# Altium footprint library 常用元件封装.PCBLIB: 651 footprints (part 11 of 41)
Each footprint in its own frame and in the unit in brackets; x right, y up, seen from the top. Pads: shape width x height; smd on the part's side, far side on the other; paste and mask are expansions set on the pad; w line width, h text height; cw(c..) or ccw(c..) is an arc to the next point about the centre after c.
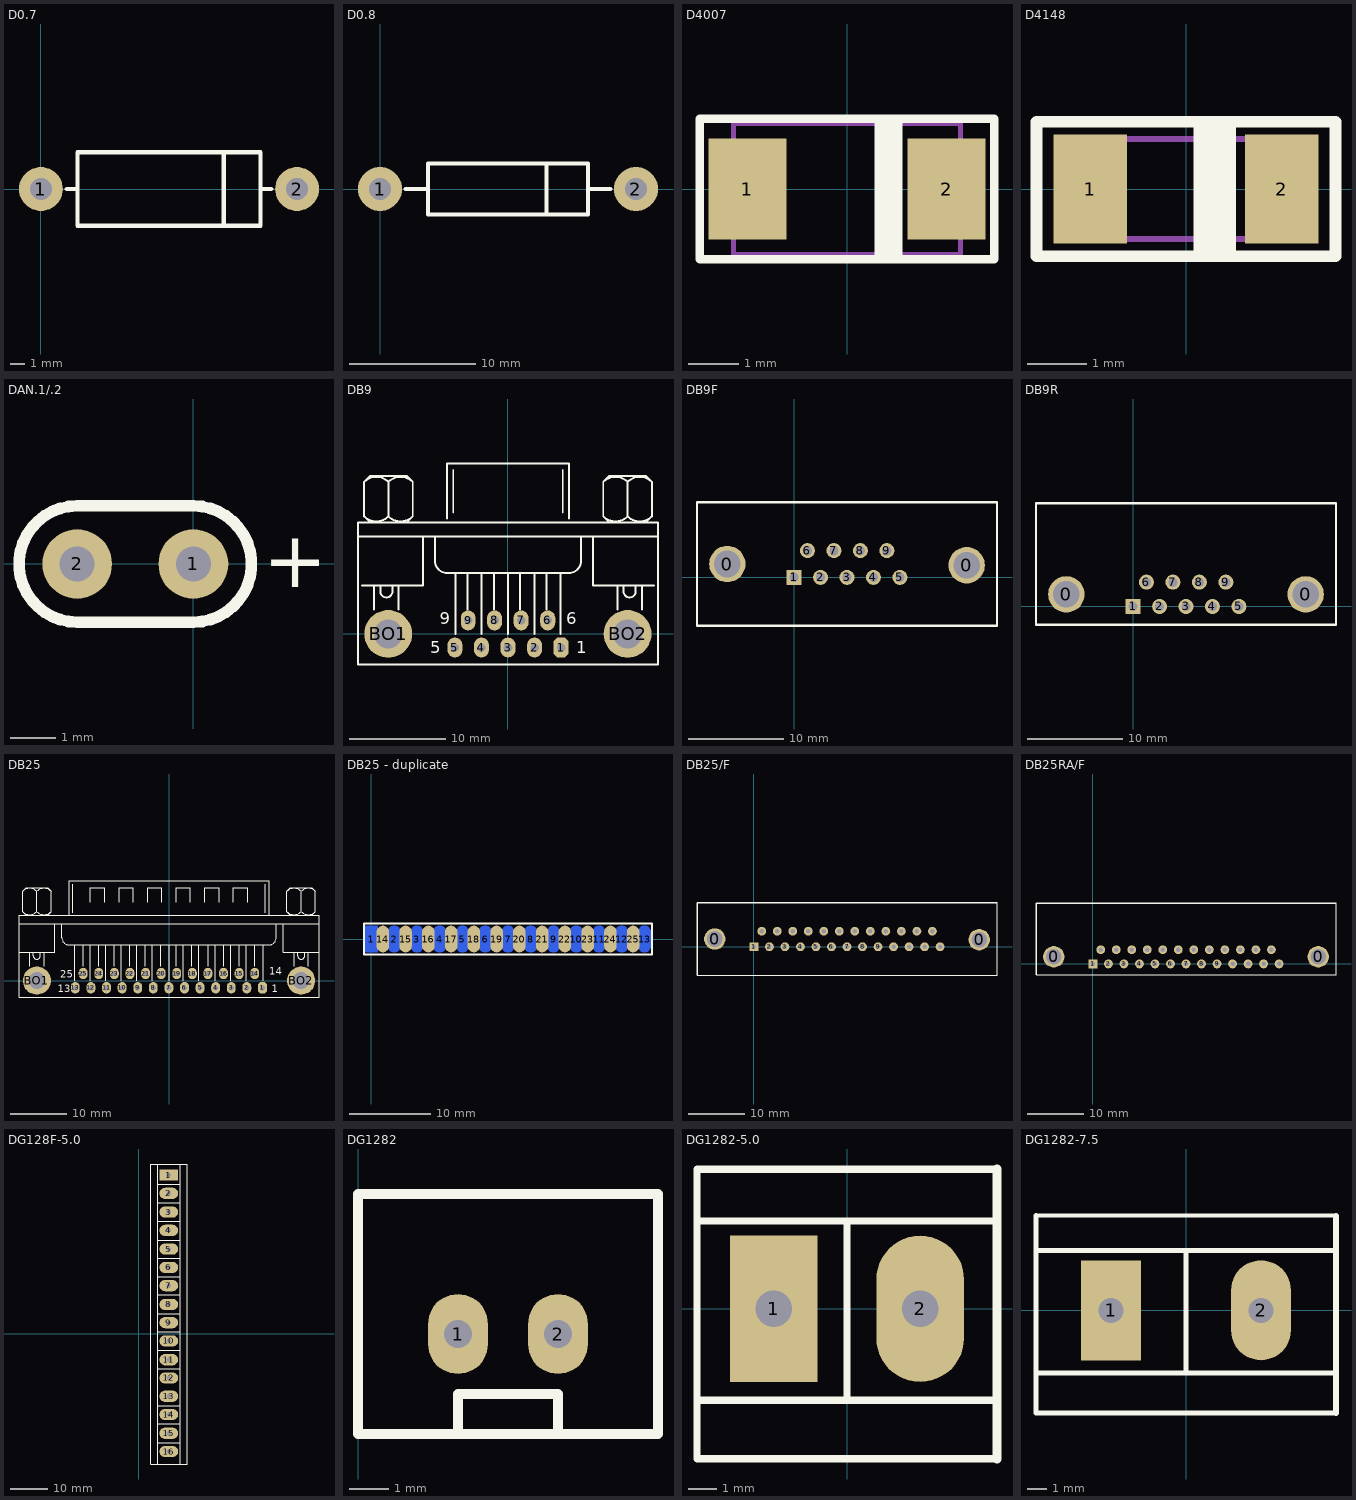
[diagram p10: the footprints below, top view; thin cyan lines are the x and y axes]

## D0.7 [mil] "17.78mm IN6A"
height 236.22
pads (2):
  round 120 hole 60: 1(0,0) 2(700,0)
TopOverlay:
  lines w12: 70,0 100,0 ; 500,-100 500,100 ; 600,0 630,0 ; 100,-100 100,100 600,100 600,-100 100,-100

## D0.8 [mm] "20.32mm"
height 6
pads (2):
  round 3.5 hole 1.78: 1(0,0) 2(20.32,0)
TopOverlay:
  lines w0.305: 2.032,0 3.81,0 ; 13.208,-2.032 13.208,2.032 ; 16.51,0 18.288,0 ; 3.81,-2.032 3.81,2.032 16.51,2.032 16.51,-2.032 3.81,-2.032

## D4007 [mm]
height 2
pads (2):
  rect 1.55x2 smd: 1(-1.975,0) 2(1.975,0)
TopOverlay:
  lines w0.17: 0.635,-1.397 0.635,1.397 ; 0.762,-1.397 0.762,1.397 ; 0.889,-1.397 0.889,1.397 ; 1.016,-1.397 1.016,1.397 ; -2.921,-1.397 2.921,-1.397 2.921,1.397 -2.921,1.397 -2.921,-1.397
Mechanical13:
  lines w0.1: -2.25,-1.3 2.25,-1.3 2.25,1.3 -2.25,1.3 -2.25,-1.3
3D body: height 2, standoff 0, extent -2.25,-1.3 2.25,1.3

## D4148 [mm] "MELF Diode, 2-Leads, Body 3.5x1.7mm, IPC Medium Density"
height 1.7
pads (2):
  rect 1.25x1.85 smd: 1(-1.625,0) 2(1.625,0)
TopOverlay:
  rectangle: 0.127,-1.143 0.854,1.143
  lines w0.2: 0.6,-1.143 2.54,-1.143 2.54,1.143 0.6,1.143 ; 0.762,-1.143 -0.6,-1.143 -2.54,-1.143 -2.54,1.143 -0.6,1.143 0.762,1.143
Mechanical13:
  rectangle: 1.352,-0.85 1.85,0.85
  lines w0.1: -1.85,-0.85 1.85,-0.85 1.85,0.85 -1.85,0.85 -1.85,-0.85
3D body: height 1.7, standoff 0, extent -1.85,-0.85 1.85,0.85

## DAN.1/.2 [mil]
pads (2):
  round 60 hole 30: 1(0,0) 2(-100,0)
TopOverlay:
  lines w10: -100,-50 cw(c-100,0) -100,50 0,50 cw(c0,0) 0,-50 -100,-50
  text "+" at 60,-20 h48

## DB9 [mil]
pads (11):
  oct 62x82 hole 35: 1(218.75,-55.83)
  oval 62x82 hole 35: 2(109.58,-55.83) 3(0.42,-55.83) 4(-108.75,-55.83) 5(-217.92,-55.83) 6(163.75,55.83) 7(54.58,55.83) 8(-54.58,55.83)
  oval 60x82 hole 35: 9(-163.75,55.83)
  round 196.67 hole 118.33: BO1(-492.08,0) BO2(492.08,0)
TopOverlay:
  lines w8: -616.25,400 617.08,400 ; -599.58,200 -349.58,200 -349.58,400 ; -591.34,483.25 ccw(c-541.25,533.33) -491.16,483.25 ; -591.34,625.09 cw(c-541.25,575) -491.16,625.09 ; -566.25,458.33 -591.25,483.33 -591.25,625 -566.25,650 -416.25,650 -391.25,625 -391.25,483.33 -416.25,458.33 ; -549.58,100 -549.58,200 ; -524.58,200 -524.58,175 ccw(c-499.58,175) -474.58,175 -474.58,200 ; -491.34,483.25 ccw(c-441.25,533.33) -391.16,483.25 ; -491.34,625.09 cw(c-441.25,575) -391.16,625.09 ; -491.25,483.33 -491.25,625 ; -449.58,100 -449.58,200 ; -299.58,400 -299.58,300 ccw(c-249.58,300) -249.58,250 250.42,250 ccw(c250.42,300) 300.42,300 300.42,400 ; -249.58,475 -249.58,700 250.42,700 250.42,475 ; -224.58,500 -224.58,675 ; -216.25,0 -216.25,250 ; -166.25,100 -166.25,250 ; -107.92,0 -107.92,250 ; -57.92,100 -57.92,250 ; 0.42,0 0.42,250 ; 50.42,100 50.42,250 ; 108.75,0 108.75,250 ; 158.75,100 158.75,250 ; 217.08,0 217.08,250 ; 225.42,500 225.42,675 ; 350.42,400 350.42,200 600.42,200 ; 392,483.25 ccw(c442.08,533.33) 492.17,483.25 ; 392,625.09 cw(c442.08,575) 492.17,625.09 ; 417.08,458.33 392.08,483.33 392.08,625 417.08,650 567.08,650 592.08,625 592.08,483.33 567.08,458.33 ; 450.42,100 450.42,200 ; 475.42,200 475.42,175 ccw(c500.42,175) 525.42,175 525.42,200 ; 492,483.25 ccw(c542.08,533.33) 592.17,483.25 ; 492,625.09 cw(c542.08,575) 592.17,625.09 ; 492.08,483.33 492.08,625 ; 550.42,100 550.42,200 ; -616.25,-125 -616.25,458.33 617.08,458.33 617.08,-125 -616.25,-125
  text "9" at -279.58,40 h50
  text "5" at -319.58,-80 h50
  text "1" at 280.42,-80 h50
  text "6" at 240.42,40 h50

## DB9F [mil]
pads (11):
  round 150 hole 110: 0(-275,55) 0(711,50)
  rect 62x62 hole 38: 1(0,0)
  round 62 hole 38: 2(109,0) 3(218,0) 4(327,0) 5(436,0) 6(55,110) 7(164,110) 8(273,110) 9(382,110)
TopOverlay:
  lines w10: -400,-200 -400,310 836,310 836,-200 -400,-200

## DB9R [mil]
pads (11):
  round 150 hole 110: 0(-275,50) 0(711,50)
  rect 62x62 hole 38: 1(0,0)
  round 62 hole 38: 2(109,0) 3(218,0) 4(327,0) 5(436,0) 6(55,100) 7(164,100) 8(273,100) 9(382,100)
TopOverlay:
  lines w10: -400,-75 -400,425 836,425 836,-75 -400,-75

## DB25 [mil]
pads (27):
  oct 62x80 hole 35: 1(654.17,-50)
  oval 62x80 hole 35: 2(545,-50) 3(435.83,-50) 4(326.67,-50) 5(217.5,-50) 6(108.33,-50) 7(-0.83,-50) 8(-110,-50) 9(-219.17,-50) 10(-328.33,-50) 11(-437.5,-50) 12(-546.67,-50) 13(-655.83,-50) 14(600,50) 15(490.83,50) 16(381.67,50) 17(272.5,50) 18(163.33,50) 19(54.17,50) 20(-55,50) 21(-164.17,50) 22(-273.33,50) 23(-382.5,50) 24(-491.67,50) 25(-600.83,50)
  round 196.67 hole 118.33: BO1(-925,0) BO2(925,0)
TopOverlay:
  lines w8: -1050,200 -800,200 -800,400 ; -1050,400 1050,400 ; -1025.09,483.25 ccw(c-975,533.33) -924.91,483.25 ; -1025.09,625.09 cw(c-975,575) -924.91,625.09 ; -1000,458.33 -1025,483.33 -1025,625 -1000,650 -850,650 -825,625 -825,483.33 -850,458.33 ; -975,100 -975,200 ; -950,200 -950,175 ccw(c-925,175) -900,175 -900,200 ; -925.09,483.25 ccw(c-875,533.33) -824.91,483.25 ; -925.09,625.09 cw(c-875,575) -824.91,625.09 ; -925,483.33 -925,625 ; -875,100 -875,200 ; -750,400 -750,300 ccw(c-700,300) -700,250 700,250 ccw(c700,300) 750,300 750,400 ; -700,458.33 -700,700 700,700 700,458.33 ; -675,475 -675,675 ; -658.33,0 -658.33,250 ; -600,100 -600,250 ; -550,0 -550,250 ; -550,550 -550,650 -450,650 -450,550 ; -491.67,100 -491.67,250 ; -441.67,0 -441.67,250 ; -383.33,100 -383.33,250 ; -350,550 -350,650 -250,650 -250,550 ; -333.33,0 -333.33,250 ; -275,100 -275,250 ; -225,0 -225,250 ; -166.67,100 -166.67,250 ; -150,550 -150,650 -50,650 -50,550 ; -116.67,0 -116.67,250 ; -58.33,100 -58.33,250 ; 0,0 0,250 ; 50,100 50,250 ; 50,550 50,650 150,650 150,550 ; 100,0 100,250 ; 158.33,100 158.33,250 ; 208.33,0 208.33,250 ; 250,550 250,650 350,650 350,550 ; 275,100 275,250 ; 325,0 325,250 ; 383.33,100 383.33,250 ; 433.33,0 433.33,250 ; 450,550 450,650 550,650 550,550 ; 491.67,100 491.67,250 ; 541.67,0 541.67,250 ; 600,100 600,250 ; 658.33,0 658.33,250 ; 675,475 675,675 ; 800,400 800,200 1050,200 ; 824.91,483.25 ccw(c875,533.33) 925.09,483.25 ; 824.91,625.09 cw(c875,575) 925.09,625.09 ; 850,458.33 825,483.33 825,625 850,650 1000,650 1025,625 1025,483.33 1000,458.33 ; 875,100 875,200 ; 900,200 900,175 ccw(c925,175) 950,175 950,200 ; 924.91,483.25 ccw(c975,533.33) 1025.09,483.25 ; 924.91,625.09 cw(c975,575) 1025.09,625.09 ; 925,483.33 925,625 ; 975,100 975,200 ; -1050,-116.67 -1050,458.33 1050,458.33 1050,-116.67 -1050,-116.67
  text "14" at 700,40 h50
  text "1" at 720,-80 h50
  text "13" at -780,-80 h50
  text "25" at -760,20 h50

## DB25 - duplicate [mil]
pads (25):
  rect 60x130 smd far side: 1(0,0)
  oval 60x130 smd far side: 2(110,0) 3(220,0) 4(330,0) 5(440,0) 6(550,0) 7(660,0) 8(770,0) 9(880,0) 10(990,0) 11(1100,0) 12(1210,0) 13(1320,0)
  oval 60x130 smd: 14(55,0) 15(165,0) 16(275,0) 17(385,0) 18(495,0) 19(605,0) 20(715,0) 21(825,0) 22(935,0) 23(1045,0) 24(1155,0) 25(1265,0)
TopOverlay:
  lines w10: -35,-75 -35,75 1355,75 1355,-75 -35,-75

## DB25/F [mil]
pads (27):
  round 150 hole 110: 0(-275,55) 0(1583,50)
  rect 62x62 hole 32: 1(0,0)
  round 62 hole 32: 2(109,0) 3(218,0) 4(327,0) 5(436,0) 6(545,0) 7(654,0) 8(763,0) 9(872,0) 10(981,0) 11(1090,0) 12(1199,0) 13(1308,0) 14(55,110) 15(164,110) 16(273,110) 17(382,110) 18(491,110) 19(600,110) 20(709,110) 21(818,110) 22(927,110) 23(1036,110) 24(1145,110) 25(1254,110)
TopOverlay:
  lines w8: -400,-200 1708,-200 1708,310
  lines w10: -400,-200 -400,310 1708,310

## DB25RA/F [mil]
pads (27):
  round 150 hole 110: 0(-275,50) 0(1583,50)
  rect 62x62 hole 32: 1(0,0)
  round 62 hole 32: 2(109,0) 3(218,0) 4(327,0) 5(436,0) 6(545,0) 7(654,0) 8(763,0) 9(872,0) 10(981,0) 11(1090,0) 12(1199,0) 13(1308,0) 14(55,100) 15(164,100) 16(273,100) 17(382,100) 18(491,100) 19(600,100) 20(709,100) 21(818,100) 22(927,100) 23(1036,100) 24(1145,100) 25(1254,100)
TopOverlay:
  lines w8: -400,-75 1708,-75 1708,425
  lines w10: -400,-75 -400,425 1708,425

## DG128F-5.0 [mil]
pads (16):
  rect 200x120 hole 50: 1(320,1693)
  oval 200x120 hole 50: 2(320,1498) 3(320,1298) 4(320,1103) 5(320,903) 6(320,708) 7(320,513) 8(320,313) 9(320,118) 10(320,-77) 11(320,-277) 12(320,-472) 13(320,-667) 14(320,-862) 15(320,-1062) 16(320,-1257)
TopOverlay:
  lines w12: 203,1594 438,1594 ; 204,-1390 204,1811 ; 208,-1161 438,-1161 ; 208,-961 438,-961 ; 208,-766 438,-766 ; 208,-376 438,-376 ; 208,-176 438,-176 ; 208,19 438,19 ; 208,214 438,214 ; 208,414 438,414 ; 208,609 438,609 ; 208,804 438,804 ; 208,999 438,999 ; 208,1199 438,1199 ; 208,1399 438,1399 ; 440,-1390 440,1811 ; 125,-1390 519,-1390 519,1811 125,1811 125,-1390

## DG1282 [mil]
pads (2):
  oval 60x80 hole 27.56: 1(100,360) 2(200,360)
TopOverlay:
  lines w10: 100,260 100,300 200,300 200,280 200,260 ; 0,260 300,260 300,500 0,500 0,380 0,260

## DG1282-5.0 [mil]
pads (2):
  rect 120x200 hole 50: 1(-100,0)
  oval 120x200 hole 50: 2(100,0)
TopOverlay:
  lines w10: -205,-203 -205,-205 205,-205 ; -205,-200 -205,191 205,191 ; -205,-125 205,-125 ; -205,120 205,120 ; 0,-124 0,120
  lines w12: 205,-205 205,191

## DG1282-7.5 [mil]
pads (2):
  rect 120x200 hole 50: 1(-150,0)
  oval 120x200 hole 50: 2(150,0)
TopOverlay:
  lines w10: -300,-125 300,-125 ; -300,120 300,120 ; -300,186 -300,-205 300,-205 ; -300,190 300,189 ; 0,-124 0,120
  lines w12: 300,-205 300,189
